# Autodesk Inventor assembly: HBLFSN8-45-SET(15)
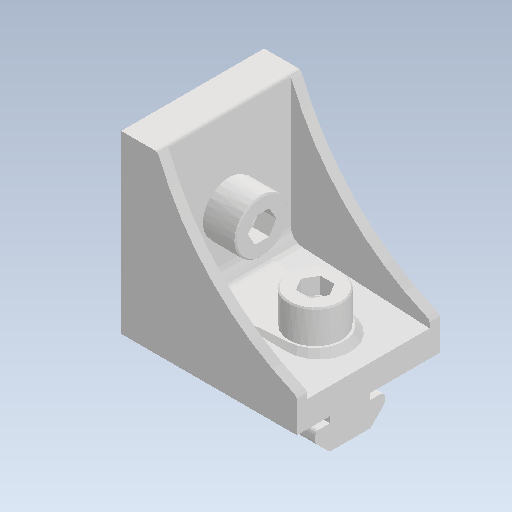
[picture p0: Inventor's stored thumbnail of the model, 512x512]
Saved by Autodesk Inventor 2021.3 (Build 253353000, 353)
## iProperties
Created: 2022-02
Part Number: HBLFSN8-45-SET(15)
Document SubType Name: Assembly
Designer: kengo
Author: kengo
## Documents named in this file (4)
- C:\Users\kengo\Documents\S2S_frame\SDC345\frame_misumi_ver12\HBLFSN8-45-SET(15).iam
- C:\Users\kengo\Documents\S2S_frame\SDC345\frame_misumi_ver12\HBLFSN8-45.ipt
- C:\Users\kengo\Documents\S2S_frame\SDC345\frame_misumi_ver12\HNTT8-8.ipt
- C:\Users\kengo\Documents\S2S_frame\SDC345\frame_misumi_ver12\CBM8-20.ipt
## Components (5 placed, 3 different names)
1. HBLFSN8-45
2. HNTT8-8
3. CBM8-20
4. HNTT8-8:1
5. CBM8-20:1
